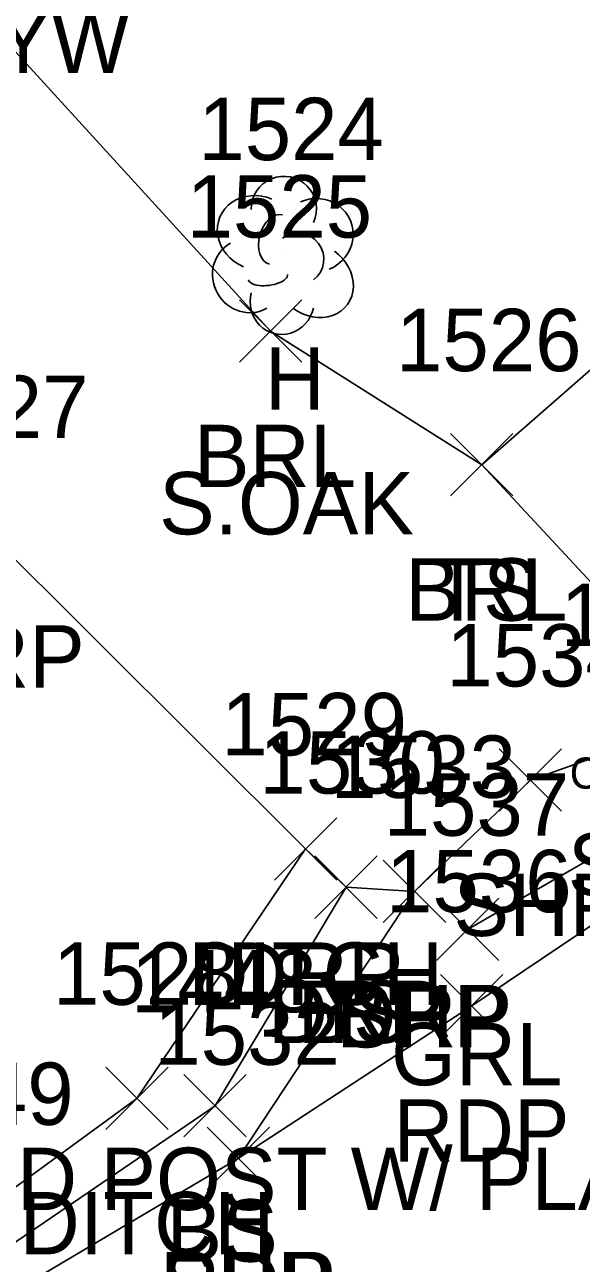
# Model space of a CAD drawing. Extents: x 1647133 to 1649138, y 411736 to 414924.
# Drawn here: x 1648810.32 to 1648828.16, y 412085.76 to 412125.47 of the extents above; entities that cross this region are included whole.
import ezdxf

# ---------------------------------------------------------------- set-up
doc = ezdxf.new("R2010")
doc.units = 0
for name, color, linetype in [('B_C', 7, 'Continuous'), ('D_A', 7, 'Continuous'), ('D_I', 7, 'Continuous'), ('D_TIC', 7, 'Continuous'), ('DD', 7, 'Continuous'), ('L_A', 7, 'Continuous'), ('L_C', 7, 'Continuous'), ('L_I', 7, 'Continuous'), ('L_TIC', 7, 'Continuous'), ('LABL', 7, 'Continuous'), ('LELB', 7, 'Continuous'), ('LTD', 7, 'Continuous'), ('P_A', 7, 'Continuous'), ('P_I', 7, 'Continuous'), ('P_TIC', 7, 'Continuous'), ('PET', 7, 'Continuous'), ('PSP', 7, 'Continuous'), ('R_A', 7, 'Continuous'), ('R_C', 7, 'Continuous'), ('R_I', 7, 'Continuous'), ('R_TIC', 7, 'Continuous'), ('RDP', 7, 'Continuous'), ('RGR', 7, 'Continuous'), ('U_A', 7, 'Continuous')]:
    doc.layers.add(name, color=color, linetype=linetype)

msp = doc.modelspace()

# ---------------------------------------------------------------- linework, layer by layer
at = {"layer": 'D_TIC'}
for points in [[(1648818.325, 412098.049), (1648820.325, 412100.049)], [(1648820.325, 412098.049), (1648818.325, 412100.049)], [(1648812.917, 412090.05), (1648814.917, 412092.05)], [(1648814.917, 412090.05), (1648812.917, 412092.05)]]:
    msp.add_lwpolyline(points, dxfattribs=at)
at = {"layer": 'DD'}
msp.add_lwpolyline([(1648803.463, 412083.836), (1648808.637, 412087.198), (1648813.917, 412091.05), (1648819.325, 412099.049)], dxfattribs=at)
at = {"layer": 'L_TIC'}
for points in [[(1648817.199, 412114.65), (1648819.199, 412116.65)], [(1648819.199, 412114.65), (1648817.199, 412116.65)], [(1648823.968, 412110.366), (1648825.968, 412112.366)], [(1648825.968, 412110.366), (1648823.968, 412112.366)], [(1648823.968, 412110.366), (1648825.968, 412112.366)], [(1648825.968, 412110.366), (1648823.968, 412112.366)], [(1648819.622, 412096.822), (1648821.622, 412098.822)], [(1648821.622, 412096.822), (1648819.622, 412098.822)], [(1648815.422, 412089.813), (1648817.422, 412091.813)], [(1648817.422, 412089.813), (1648815.422, 412091.813)]]:
    msp.add_lwpolyline(points, dxfattribs=at)
at = {"layer": 'LABL'}
msp.add_lwpolyline([(1648799.847, 412141.142), (1648807.127, 412127.778), (1648818.199, 412115.65), (1648824.968, 412111.366), (1648838.944, 412123.578)], dxfattribs=at)
at = {"layer": 'LELB'}
for points in [[(1648824.968, 412111.366), (1648830.891, 412104.998)], [(1648804.397, 412082.609), (1648816.422, 412090.813), (1648820.622, 412097.822)]]:
    msp.add_lwpolyline(points, dxfattribs=at)
at = {"layer": 'LTD'}
msp.add_line((1648818.578, 412118.133), (1648818.578, 412118.133), dxfattribs=at)
msp.add_line((1648818.578, 412118.133), (1648818.578, 412118.133), dxfattribs=at)
msp.add_arc((1648818.625, 412119.567), 1.047, 335.5272, 180.9563, dxfattribs=at)
for centre, major_axis, ratio, start_param, end_param in [((1648817.786, 412118.799), (1.21, -0.512), 0.895232, 1.570796, 4.712389), ((1648819.619, 412118.716), (-1.141, -0.483), 0.949671, 1.570796, 4.712389), ((1648818.369, 412118.591), (-0.208, -0.792), 0.645439, 3.141593, 6.283185), ((1648819.078, 412117.966), (-0.5, 0.667), 0.989748, 3.141593, 6.283185), ((1648817.495, 412117.424), (0.584, -1.042), 0.959034, 3.141593, 6.283185), ((1648819.578, 412117.3), (-1.09, 0.792), 0.841452, 1.570796, 4.712389), ((1648818.12, 412117.383), (-0.625, -0.083), 0.423636, 0, 3.141593), ((1648818.578, 412116.633), (0.265, 1.061), 0.942809, 1.570796, 4.712389)]:
    msp.add_ellipse(centre, major_axis=major_axis, ratio=ratio, start_param=start_param, end_param=end_param, dxfattribs=at)
at = {"layer": 'P_TIC'}
for points in [[(1648825.528, 412100.257), (1648827.528, 412102.257)], [(1648827.528, 412100.257), (1648825.528, 412102.257)], [(1648821.814, 412096.685), (1648823.814, 412098.685)], [(1648823.814, 412096.685), (1648821.814, 412098.685)], [(1648823.651, 412093.018), (1648825.651, 412095.018)], [(1648825.651, 412093.018), (1648823.651, 412095.018)], [(1648816.165, 412088.126), (1648818.165, 412090.126)], [(1648818.165, 412088.126), (1648816.165, 412090.126)], [(1648816.165, 412088.126), (1648818.165, 412090.126)], [(1648818.165, 412088.126), (1648816.165, 412090.126)]]:
    msp.add_lwpolyline(points, dxfattribs=at)
at = {"layer": 'PET'}
msp.add_lwpolyline([(1648804.077, 412081.379), (1648817.165, 412089.126), (1648824.651, 412094.018), (1648832.497, 412099.297), (1648836.674, 412102.355), (1648842.257, 412096.253), (1648847.201, 412090.123), (1648841.152, 412084.448), (1648829.009, 412072.706), (1648818.716, 412064.019)], dxfattribs=at)
at = {"layer": 'PSP'}
msp.add_lwpolyline([(1648817.165, 412089.126), (1648822.814, 412097.685), (1648826.528, 412101.257), (1648830.193, 412102.555), (1648831.501, 412103.876)], dxfattribs=at)
at = {"layer": 'R_TIC'}
for points in [[(1648818.325, 412098.049), (1648820.325, 412100.049)], [(1648820.325, 412098.049), (1648818.325, 412100.049)], [(1648819.622, 412096.822), (1648821.622, 412098.822)], [(1648821.622, 412096.822), (1648819.622, 412098.822)], [(1648821.814, 412096.685), (1648823.814, 412098.685)], [(1648823.814, 412096.685), (1648821.814, 412098.685)], [(1648823.517, 412095.47), (1648825.517, 412097.47)], [(1648825.517, 412095.47), (1648823.517, 412097.47)]]:
    msp.add_lwpolyline(points, dxfattribs=at)
at = {"layer": 'RDP'}
msp.add_lwpolyline([(1648808.637, 412087.198), (1648800.581, 412101.88), (1648792.637, 412116.358), (1648777.478, 412142.603), (1648782.888, 412146.657), (1648798.186, 412123.321), (1648809.106, 412109.222), (1648819.325, 412099.049), (1648820.622, 412097.822), (1648822.814, 412097.685)], dxfattribs=at)
at = {"layer": 'RGR'}
msp.add_lwpolyline([(1648824.517, 412096.47), (1648833.997, 412101.912)], dxfattribs=at)

# ---------------------------------------------------------------- texts
at = {"layer": 'B_C'}
msp.add_text('CONCRETE', height=1, dxfattribs=at).set_placement((1648827.791, 412100.98))
at = {"layer": 'D_A'}
for p in [(1648815.561, 412094.049), (1648810.153, 412086.05)]:
    msp.add_text('DITCH', height=2, dxfattribs=at).set_placement(p)
at = {"layer": 'D_I'}
for s, p in [('1529', (1648816.624, 412102.049)), ('1528', (1648811.224, 412094.05)), ('1449', (1648805.936, 412090.198))]:
    msp.add_text(s, height=2, dxfattribs=at).set_placement(p)
at = {"layer": 'L_A'}
for s, p in [('H', (1648818.011, 412113.133)), ('BRL', (1648815.742, 412110.65)), ('BRL', (1648822.511, 412106.366)), ('TS', (1648823.377, 412106.366)), ('BS', (1648819.063, 412092.822)), ('BS', (1648814.863, 412085.813))]:
    msp.add_text(s, height=2, dxfattribs=at).set_placement(p)
at = {"layer": 'L_C'}
msp.add_text('S.OAK', height=2, dxfattribs=at).set_placement((1648814.625, 412109.133))
at = {"layer": 'L_I'}
for s, p in [('1524', (1648815.885, 412121.133)), ('1525', (1648815.506, 412118.65)), ('1526', (1648822.22, 412114.366)), ('1526', (1648822.22, 412114.366)), ('1530', (1648817.843, 412100.822)), ('1448', (1648813.729, 412093.813))]:
    msp.add_text(s, height=2, dxfattribs=at).set_placement(p)
at = {"layer": 'P_A'}
for s, p in [('SHP', (1648827.728, 412097.555)), ('SHP', (1648824.064, 412096.257)), ('SHP', (1648820.35, 412092.685)), ('RDP', (1648822.139, 412089.018)), ('SHP', (1648814.7, 412084.126)), ('RDP', (1648814.653, 412084.126))]:
    msp.add_text(s, height=2, dxfattribs=at).set_placement(p)
at = {"layer": 'P_I'}
for s, p in [('1535', (1648827.5, 412105.555)), ('1534', (1648823.835, 412104.257)), ('1533', (1648820.121, 412100.685)), ('1536', (1648821.902, 412097.018)), ('1532', (1648814.472, 412092.126)), ('1532', (1648814.472, 412092.126))]:
    msp.add_text(s, height=2, dxfattribs=at).set_placement(p)
at = {"layer": 'R_A'}
for s, p in [('DRP', (1648806.594, 412104.222)), ('DRP', (1648816.813, 412094.049)), ('DRP', (1648818.111, 412092.822)), ('DRP', (1648820.302, 412092.685)), ('GRL', (1648822.06, 412091.47))]:
    msp.add_text(s, height=2, dxfattribs=at).set_placement(p)
at = {"layer": 'R_C'}
msp.add_text('WOOD POST W/ PLANK RAIL', height=2, dxfattribs=at).set_placement((1648803.383, 412087.47))
at = {"layer": 'R_I'}
for s, p in [('1527', (1648806.413, 412112.222)), ('1529', (1648816.624, 412102.049)), ('1530', (1648817.843, 412100.822)), ('1533', (1648820.121, 412100.685)), ('1537', (1648821.824, 412099.47)), ('1449', (1648805.936, 412090.198))]:
    msp.add_text(s, height=2, dxfattribs=at).set_placement(p)
at = {"layer": 'U_A'}
msp.add_text('GUYW', height=2, dxfattribs=at).set_placement((1648805.369, 412123.925))

doc.saveas('drawing.dxf')
